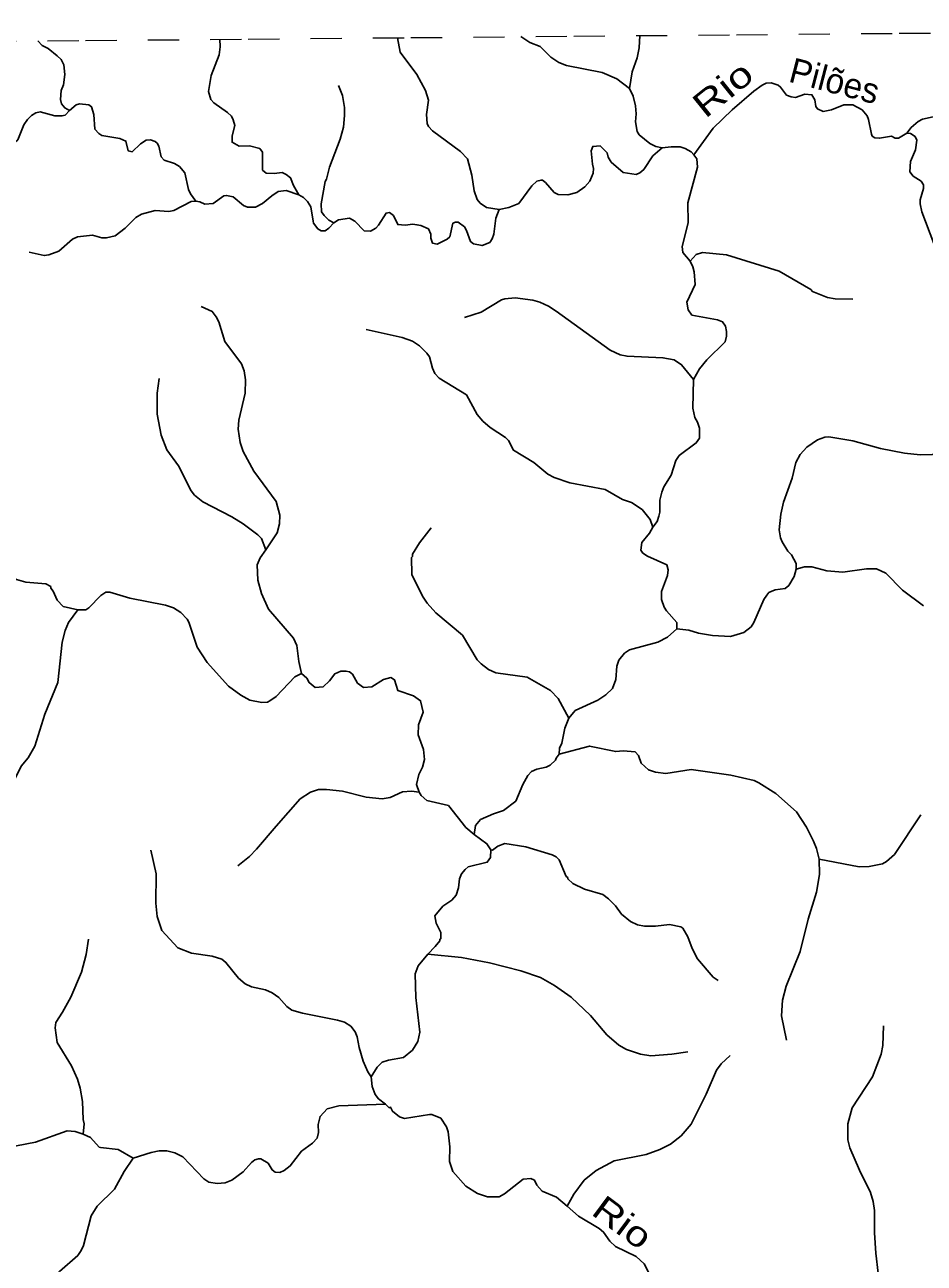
# Model space of a CAD drawing. Extents: x 346.5 to 372.4, y 7400.3 to 7428.2.
# Drawn here: x 366.191 to 369.076, y 7424.274 to 7428.245 of the extents above; entities that cross this region are included whole.
import ezdxf
from ezdxf.enums import TextEntityAlignment as Align

# ---------------------------------------------------------------- set-up
doc = ezdxf.new("R2010")
doc.units = 0
doc.header["$LTSCALE"] = 0.032
doc.linetypes.add('SHORT_DASHED', pattern=[2.7, 1.5, -1.2])
doc.layers.add('53', color=7, linetype='SHORT_DASHED', lineweight=13)
doc.layers.add('7', color=7, linetype='Continuous', lineweight=25)
doc.layers.add('61', color=7, linetype='Continuous')

msp = doc.modelspace()

# ---------------------------------------------------------------- linework, layer by layer
at = {"layer": '53'}
msp.add_lwpolyline([(361.6878, 7428.1517), (362.2098, 7428.1565), (362.7318, 7428.1614), (363.2538, 7428.1662), (363.7758, 7428.171), (364.2978, 7428.1758), (364.8198, 7428.1805), (365.3418, 7428.1853), (365.8638, 7428.19), (366.3858, 7428.1947), (366.9078, 7428.1994), (367.4298, 7428.2041), (367.9518, 7428.2087), (368.4738, 7428.2133), (368.9958, 7428.218), (369.5177, 7428.2225), (370.0397, 7428.2271), (370.5617, 7428.2317), (371.0837, 7428.2362), (371.6057, 7428.2408), (372.1277, 7428.2453)], dxfattribs=at)
at = {"layer": '7'}
for points in [[(366.2331, 7428.1933), (366.2471, 7428.1793), (366.2654, 7428.169), (366.2949, 7428.1459), (366.3076, 7428.1339), (366.3164, 7428.1172), (366.3196, 7428.0853), (366.3156, 7428.0526), (366.3076, 7428.0343), (366.3052, 7428.0056), (366.3084, 7427.9913), (366.3191, 7427.9786), (366.3339, 7427.9699)], [(366.8162, 7428.1986), (366.8177, 7428.1746), (366.8145, 7428.1491), (366.789, 7428.0821), (366.7802, 7428.0311), (366.7874, 7428.0056), (366.797, 7427.9953), (366.8416, 7427.9642), (366.8543, 7427.9522), (366.8599, 7427.9403), (366.8647, 7427.9219), (366.8567, 7427.8893), (366.8559, 7427.8685), (366.879, 7427.8558), (366.9117, 7427.8566), (366.9444, 7427.8486), (366.954, 7427.8367), (366.9532, 7427.7793), (366.9651, 7427.7697), (366.9914, 7427.7681), (367.0169, 7427.7713), (367.0297, 7427.7649), (367.0432, 7427.7546), (367.0528, 7427.7299), (367.0697, 7427.7)], [(367.3864, 7428.2037), (367.3947, 7428.157), (367.4489, 7428.0853), (367.4767, 7428.0343), (367.4855, 7428.004), (367.4791, 7427.9578), (367.4815, 7427.9291), (367.4855, 7427.9187), (367.4983, 7427.9052), (367.5883, 7427.8391), (367.6114, 7427.8151), (367.625, 7427.7634), (367.6321, 7427.7123), (367.6417, 7427.6852), (367.6521, 7427.6733), (367.672, 7427.6589), (367.7128, 7427.6526)], [(367.7823, 7428.2072), (367.8107, 7428.1881), (367.8442, 7428.1754), (367.8784, 7428.1411), (367.9039, 7428.1244), (367.9286, 7428.1148), (368.0434, 7428.0925), (368.0904, 7428.0718), (368.1312, 7428.0405)], [(368.1636, 7428.2105), (368.1613, 7428.1714), (368.1549, 7428.1395), (368.139, 7428.0949), (368.1312, 7428.0405)], [(367.197, 7428.051), (367.2098, 7428.0184), (367.2161, 7427.9801), (367.2169, 7427.9546), (367.213, 7427.9164), (367.2026, 7427.8781), (367.1683, 7427.7889), (367.1588, 7427.7506), (367.154, 7427.7426), (367.142, 7427.6709), (367.1428, 7427.6454), (367.1508, 7427.6334), (367.1667, 7427.6191), (367.1828, 7427.6098)], [(368.1312, 7428.0405), (368.1422, 7428.016), (368.1502, 7427.9849), (368.1526, 7427.9594), (368.1502, 7427.9339), (368.1549, 7427.9028), (368.1613, 7427.8925), (368.1964, 7427.8645), (368.2155, 7427.855), (368.2352, 7427.8506)], [(369.0208, 7427.8978), (368.9934, 7427.8813), (368.983, 7427.8813), (368.971, 7427.8877), (368.9328, 7427.8813), (368.9176, 7427.8829), (368.9089, 7427.8885), (368.9065, 7427.8941), (368.8977, 7427.9419), (368.8929, 7427.9538), (368.877, 7427.9721), (368.8467, 7427.9881), (368.818, 7427.9889), (368.7782, 7427.9721), (368.7519, 7427.9674), (368.7335, 7427.9753), (368.7288, 7427.9833), (368.7256, 7428.0048), (368.716, 7428.0207), (368.6937, 7428.0223), (368.6634, 7428.012), (368.6491, 7428.0144), (368.6347, 7428.0192), (368.6156, 7428.0454), (368.6076, 7428.0518), (368.5853, 7428.059), (368.5694, 7428.0582), (368.5558, 7428.0518), (368.5295, 7428.0327), (368.4602, 7427.9721), (368.3996, 7427.9132), (368.3373, 7427.8283)], [(366.3339, 7427.9699), (366.3204, 7427.9554), (366.31, 7427.953), (366.2869, 7427.9538), (366.2407, 7427.9658), (366.2263, 7427.9626), (366.2128, 7427.9546), (366.2, 7427.9419), (366.1881, 7427.9243), (366.1682, 7427.8765), (366.1602, 7427.8685), (366.1275, 7427.8494), (366.0765, 7427.8279), (366.0231, 7427.7992), (366.0007, 7427.7855), (365.9865, 7427.7783)], [(366.7396, 7427.6792), (366.722, 7427.7028), (366.7157, 7427.7171), (366.7045, 7427.7705), (366.687, 7427.7904), (366.6711, 7427.8), (366.6376, 7427.8112), (366.6288, 7427.8223), (366.6208, 7427.8558), (366.6153, 7427.8661), (366.6089, 7427.8709), (366.5945, 7427.8765), (366.5802, 7427.8749), (366.5619, 7427.863), (366.5356, 7427.8382), (366.5228, 7427.8406), (366.5156, 7427.8725), (366.4957, 7427.8805), (366.4383, 7427.8901), (366.428, 7427.8964), (366.416, 7427.91), (366.4128, 7427.9578), (366.4049, 7427.9825), (366.3969, 7427.9881), (366.3666, 7427.9921), (366.3562, 7427.9881), (366.3339, 7427.9699)], [(369.1045, 7427.9498), (369.0706, 7427.9426), (369.0571, 7427.9347), (369.0347, 7427.9155), (369.0208, 7427.8978)], [(369.0208, 7427.8978), (369.0316, 7427.8964), (369.0467, 7427.8869), (369.0523, 7427.8757), (369.0483, 7427.8446), (369.0316, 7427.8064), (369.03, 7427.7737), (369.0412, 7427.7601), (369.0667, 7427.7434), (369.0738, 7427.7315), (369.0738, 7427.7203), (369.0635, 7427.6837), (369.0627, 7427.6709), (369.0682, 7427.6454), (369.1073, 7427.5434)], [(367.7128, 7427.6526), (367.7437, 7427.6589), (367.7756, 7427.6717), (367.817, 7427.7283), (367.8338, 7427.7442), (367.8473, 7427.7474), (367.8521, 7427.7474), (367.8617, 7427.7394), (367.8888, 7427.7076), (367.9015, 7427.7012), (367.9334, 7427.7004), (367.9621, 7427.7075), (367.9876, 7427.7251), (368.0035, 7427.7434), (368.0139, 7427.7697), (368.0155, 7427.7841), (368.0123, 7427.7984), (368.0075, 7427.8415), (368.0131, 7427.855), (368.037, 7427.8566), (368.0593, 7427.8343), (368.0625, 7427.8207), (368.0721, 7427.8048), (368.1103, 7427.7713), (368.1518, 7427.7649), (368.1637, 7427.7705), (368.1765, 7427.7817), (368.2052, 7427.8247), (368.2352, 7427.8506)], [(368.2352, 7427.8506), (368.2649, 7427.8542), (368.2936, 7427.8534), (368.3096, 7427.8486), (368.3287, 7427.8375), (368.3373, 7427.8283)], [(368.3373, 7427.8283), (368.3469, 7427.8152), (368.3486, 7427.7889), (368.3183, 7427.6741), (368.3191, 7427.6103), (368.3, 7427.5338), (368.3016, 7427.5147), (368.3252, 7427.487)], [(366.7396, 7427.6792), (366.7244, 7427.6787), (366.6695, 7427.6502), (366.6535, 7427.647), (366.6089, 7427.6502), (366.565, 7427.6382), (366.5475, 7427.6271), (366.5132, 7427.5928), (366.4806, 7427.5681), (366.4527, 7427.5625), (366.4383, 7427.5625), (366.4081, 7427.5705), (366.3602, 7427.5649), (366.3443, 7427.5577), (366.2997, 7427.5195), (366.2678, 7427.5075), (366.2535, 7427.5051), (366.2048, 7427.5163)], [(367.0697, 7427.7), (367.0297, 7427.7139), (367.0042, 7427.7107), (366.9835, 7427.6972), (366.954, 7427.6717), (366.9309, 7427.6605), (366.9054, 7427.6605), (366.8926, 7427.6661), (366.8599, 7427.694), (366.8384, 7427.698), (366.8296, 7427.6972), (366.7954, 7427.6717), (366.7685, 7427.6697), (366.7526, 7427.678), (366.7396, 7427.6792)], [(367.1828, 7427.6098), (367.1667, 7427.5928), (367.154, 7427.5848), (367.1412, 7427.5848), (367.1309, 7427.5904), (367.1173, 7427.6087), (367.1165, 7427.6159), (367.1086, 7427.6613), (367.0982, 7427.6781), (367.085, 7427.6916), (367.0697, 7427.7)], [(367.7128, 7427.6526), (367.7015, 7427.6247), (367.6959, 7427.5737), (367.6903, 7427.5585), (367.6824, 7427.5474), (367.6577, 7427.537), (367.6306, 7427.5426), (367.621, 7427.5498), (367.6082, 7427.5856), (367.6011, 7427.5968), (367.5812, 7427.6127), (367.5724, 7427.6127), (367.5644, 7427.6087), (367.5549, 7427.5657), (367.5461, 7427.5577), (367.5142, 7427.5418), (367.4983, 7427.545), (367.4935, 7427.5609), (367.4935, 7427.5737), (367.4855, 7427.5904), (367.4616, 7427.6016), (367.4489, 7427.6039), (367.4361, 7427.6055), (367.4106, 7427.6023), (367.3875, 7427.6047), (367.374, 7427.6334), (367.3612, 7427.6438), (367.35, 7427.6414), (367.3261, 7427.6024), (367.3174, 7427.5928), (367.2998, 7427.5832), (367.2799, 7427.5848), (367.2496, 7427.6159), (367.2329, 7427.6247), (367.1973, 7427.6202), (367.1828, 7427.6098)], [(368.3252, 7427.487), (368.3341, 7427.4691), (368.3382, 7427.4525), (368.3414, 7427.4119), (368.3151, 7427.3561), (368.3191, 7427.3314), (368.3311, 7427.3138), (368.4132, 7427.2995), (368.4291, 7427.2923), (368.4387, 7427.2788), (368.4418, 7427.2613), (368.4418, 7427.2469), (368.4371, 7427.2286), (368.3789, 7427.1712), (368.3558, 7427.1417), (368.3364, 7427.1079)], [(368.3252, 7427.487), (368.3446, 7427.5083), (368.3654, 7427.5155), (368.4419, 7427.5075), (368.6108, 7427.4549), (368.7128, 7427.3959), (368.7176, 7427.3904), (368.7654, 7427.3712), (368.7909, 7427.3665), (368.8475, 7427.3649)], [(367.6011, 7427.3067), (367.6545, 7427.3242), (367.7198, 7427.3633), (367.731, 7427.3665), (367.7645, 7427.3696), (367.8202, 7427.3625), (367.8426, 7427.3561), (367.8705, 7427.3433), (367.8951, 7427.3274), (368.0689, 7427.2015), (368.1008, 7427.1871), (368.1231, 7427.1824), (368.2378, 7427.1776), (368.2745, 7427.1712), (368.2976, 7427.1553), (368.3364, 7427.1079)], [(366.7563, 7427.3418), (366.7922, 7427.3258), (366.8049, 7427.3091), (366.8137, 7427.2932), (366.8328, 7427.2294), (366.8862, 7427.1585), (366.8942, 7427.1354), (366.899, 7427.1067), (366.8974, 7427.0636), (366.8774, 7426.9776), (366.8751, 7426.9489), (366.8814, 7426.9058), (366.891, 7426.8771), (366.9261, 7426.8134), (366.997, 7426.7162), (367.0089, 7426.6731), (367.0081, 7426.6444), (367.001, 7426.6157), (366.9646, 7426.5619)], [(367.2855, 7427.2677), (367.4011, 7427.2429), (367.4345, 7427.2302), (367.4568, 7427.2158), (367.4807, 7427.1927), (367.4887, 7427.18), (367.4983, 7427.1441), (367.5062, 7427.1266), (367.5206, 7427.1122), (367.6074, 7427.0581), (367.6425, 7426.9959), (367.6601, 7426.9744), (367.684, 7426.9536), (367.7334, 7426.9218), (367.7421, 7426.9122), (367.7581, 7426.8811), (367.8242, 7426.8421), (367.8689, 7426.8038), (367.8888, 7426.7935), (367.9398, 7426.7759), (368.0522, 7426.7552), (368.1087, 7426.7233), (368.1374, 7426.713), (368.1709, 7426.6906), (368.1972, 7426.6588), (368.2053, 7426.6343)], [(366.6216, 7427.1106), (366.6153, 7427.0636), (366.6153, 7426.9967), (366.6288, 7426.9297), (366.6463, 7426.8819), (366.6838, 7426.8309), (366.7244, 7426.7504), (366.7356, 7426.7369), (366.7619, 7426.7154), (366.8551, 7426.6675), (366.891, 7426.6452), (366.938, 7426.6094), (366.95, 7426.5974), (366.9646, 7426.5619)], [(368.3364, 7427.1079), (368.3343, 7427.0158), (368.3398, 7426.9855), (368.3494, 7426.9704), (368.3558, 7426.9521), (368.3558, 7426.9194), (368.3446, 7426.9042), (368.2896, 7426.8636), (368.2793, 7426.8477), (368.2641, 7426.8006), (368.241, 7426.7632), (368.2346, 7426.7464), (368.2283, 7426.7209), (368.2283, 7426.6827), (368.2251, 7426.6699), (368.2195, 7426.6524), (368.2053, 7426.6343)], [(369.2763, 7426.9704), (369.1527, 7426.8787), (369.1017, 7426.8668), (369.0635, 7426.866), (369.0125, 7426.8716), (368.936, 7426.8867), (368.8467, 7426.9114), (368.7702, 7426.9234), (368.7575, 7426.9226), (368.7335, 7426.9146), (368.6993, 7426.8907), (368.6785, 7426.8676), (368.6642, 7426.8421), (368.653, 7426.7911), (368.6251, 7426.7146), (368.6164, 7426.6763), (368.6108, 7426.6253), (368.6148, 7426.5998), (368.6204, 7426.5871), (368.6387, 7426.5576), (368.6499, 7426.5456), (368.6652, 7426.5179), (368.6652, 7426.5)], [(367.4943, 7426.6325), (367.4568, 7426.5839), (367.4345, 7426.5472), (367.4345, 7426.54), (367.4313, 7426.5368), (367.4321, 7426.4819), (367.4672, 7426.4125), (367.4815, 7426.3902), (367.5094, 7426.3591), (367.5955, 7426.2874), (367.6425, 7426.2085), (367.6545, 7426.1958), (367.6784, 7426.1782), (367.7023, 7426.1671), (367.8027, 7426.1535), (367.8776, 7426.1105), (367.9023, 7426.085), (367.9357, 7426.0221)], [(368.2053, 7426.6343), (368.1948, 7426.6149), (368.1701, 7426.5847), (368.1669, 7426.56), (368.1733, 7426.5512), (368.1884, 7426.5408), (368.2506, 7426.5129), (368.2546, 7426.4978), (368.2522, 7426.4787), (368.233, 7426.4277), (368.2338, 7426.4022), (368.2418, 7426.3775), (368.249, 7426.3655), (368.2825, 7426.328), (368.2821, 7426.3085)], [(366.1215, 7426.5691), (366.1215, 7426.5374), (366.1076, 7426.5145), (366.11, 7426.4946), (366.1355, 7426.4779), (366.1642, 7426.4659), (366.1945, 7426.4579), (366.2582, 7426.4524), (366.2742, 7426.4436), (366.2742, 7426.4388), (366.2821, 7426.4293), (366.2949, 7426.4006), (366.314, 7426.3798), (366.3611, 7426.3686)], [(366.9646, 7426.5619), (366.946, 7426.5361), (366.9364, 7426.5129), (366.9388, 7426.4643), (366.95, 7426.4213), (366.9723, 7426.3711), (367.0528, 7426.2778), (367.0631, 7426.2547), (367.0695, 7426.2029), (367.0783, 7426.1645)], [(368.6652, 7426.5), (368.6586, 7426.4755), (368.6419, 7426.4476), (368.6299, 7426.438), (368.5981, 7426.4332), (368.5853, 7426.4277), (368.5781, 7426.4245), (368.5717, 7426.4165), (368.5614, 7426.4022), (368.5295, 7426.3288), (368.5208, 7426.3145), (368.4977, 7426.2962), (368.4546, 7426.2834), (368.3972, 7426.2866), (368.3526, 7426.2946), (368.3207, 7426.3041), (368.2821, 7426.3085)], [(369.0738, 7426.3822), (369.0069, 7426.4324), (368.9535, 7426.4866), (368.9232, 7426.5002), (368.8913, 7426.5002), (368.8148, 7426.4898), (368.7638, 7426.4938), (368.7152, 7426.5073), (368.6921, 7426.5073), (368.6652, 7426.5)], [(366.3611, 7426.3686), (366.3865, 7426.3695), (366.3969, 7426.3751), (366.4351, 7426.4149), (366.4511, 7426.4253), (366.4638, 7426.4261), (366.5276, 7426.4061), (366.6424, 7426.3846), (366.6679, 7426.3758), (366.6918, 7426.3607), (366.7117, 7426.3392), (366.7173, 7426.3296), (366.7436, 7426.2492), (366.7762, 7426.1997), (366.844, 7426.1248), (366.8838, 7426.0953), (366.9133, 7426.0794), (366.9516, 7426.0722), (366.9691, 7426.073), (366.9771, 7426.077), (366.9978, 7426.0913), (367.0568, 7426.1543), (367.0783, 7426.1645)], [(366.3611, 7426.3686), (366.3307, 7426.3288), (366.3204, 7426.3033), (366.3108, 7426.2651), (366.2973, 7426.136), (366.255, 7426.034), (366.2231, 7425.932), (366.2016, 7425.8945), (366.1793, 7425.8682), (366.1546, 7425.8172), (366.1403, 7425.7662), (366.1323, 7425.7184), (366.1323, 7425.653), (366.1259, 7425.5893), (366.114, 7425.551), (366.0853, 7425.5088)], [(368.2821, 7426.3085), (368.2522, 7426.281), (368.2219, 7426.2659), (368.1303, 7426.2412), (368.1151, 7426.23), (368.096, 7426.2077), (368.0904, 7426.1886), (368.0864, 7426.1456), (368.0761, 7426.1168), (368.0545, 7426.0961), (368.029, 7426.0794), (367.9565, 7426.0459), (367.9357, 7426.0221)], [(367.0783, 7426.1645), (367.0958, 7426.1495), (367.103, 7426.136), (367.1221, 7426.12), (367.1476, 7426.1224), (367.1683, 7426.1416), (367.1851, 7426.1639), (367.205, 7426.1726), (367.2209, 7426.1726), (367.2321, 7426.1702), (367.2417, 7426.1623), (367.2584, 7426.1344), (367.2775, 7426.12), (367.3046, 7426.1224), (367.3421, 7426.1455), (367.3652, 7426.1519), (367.3771, 7426.1447), (367.3875, 7426.1105), (367.4377, 7426.0929), (367.4608, 7426.0778), (367.4688, 7426.0411), (367.4544, 7426.0005), (367.4528, 7425.9686), (367.4696, 7425.9208), (367.4736, 7425.8889), (367.4664, 7425.8642), (367.4552, 7425.8411), (367.4474, 7425.8092), (367.4556, 7425.7844)], [(367.9357, 7426.0221), (367.9238, 7425.9893), (367.9135, 7425.9415), (367.9067, 7425.9252), (367.9047, 7425.9066)], [(368.7387, 7425.5699), (368.7311, 7425.6036), (368.7208, 7425.6275), (368.6985, 7425.6722), (368.6666, 7425.7216), (368.5997, 7425.7805), (368.5455, 7425.8148), (368.5303, 7425.822), (368.4562, 7425.8387), (368.3287, 7425.857), (368.2474, 7425.8443), (368.2139, 7425.8483), (368.1916, 7425.8562), (368.1685, 7425.8778), (368.1597, 7425.9017), (368.1486, 7425.9136), (368.1103, 7425.9168), (368.0864, 7425.9144), (368.0027, 7425.932), (367.9047, 7425.9066)], [(367.9047, 7425.9066), (367.8951, 7425.8937), (367.8936, 7425.8865), (367.876, 7425.8714), (367.8633, 7425.8642), (367.833, 7425.8578), (367.8162, 7425.8507), (367.8051, 7425.8379), (367.7884, 7425.8092), (367.766, 7425.7558), (367.7262, 7425.7255), (367.6943, 7425.7152), (367.6529, 7425.6969), (367.637, 7425.6776), (367.6328, 7425.6484)], [(367.4556, 7425.7844), (367.4314, 7425.7872), (367.4025, 7425.7858), (367.3628, 7425.7678), (367.3373, 7425.763), (367.2863, 7425.7686), (367.2098, 7425.7877), (367.1588, 7425.7933), (367.1333, 7425.7925), (367.1078, 7425.7845), (367.0743, 7425.763), (366.9978, 7425.6754), (366.934, 7425.6012), (366.9117, 7425.5781), (366.8743, 7425.5486)], [(367.6328, 7425.6484), (367.6059, 7425.6714), (367.5501, 7425.7415), (367.481, 7425.7582), (367.4624, 7425.7734), (367.4556, 7425.7844)], [(369.0651, 7425.7112), (368.9806, 7425.5845), (368.9551, 7425.5622), (368.9423, 7425.555), (368.8993, 7425.5462), (368.8674, 7425.5454), (368.7387, 7425.5699)], [(367.6859, 7425.5992), (367.6736, 7425.6188), (367.6328, 7425.6484)], [(368.4152, 7425.1807), (368.3988, 7425.1916), (368.3486, 7425.2498), (368.3319, 7425.2833), (368.3183, 7425.3207), (368.3016, 7425.3478), (368.2952, 7425.3526), (368.2586, 7425.3605), (368.2139, 7425.3542), (368.1789, 7425.3542), (368.1566, 7425.359), (368.1342, 7425.3701), (368.1055, 7425.3932), (368.0856, 7425.4195), (368.0633, 7425.4426), (368.045, 7425.4562), (367.986, 7425.4737), (367.9493, 7425.492), (367.9326, 7425.5064), (367.9326, 7425.5104), (367.9278, 7425.5144), (367.9055, 7425.567), (367.8951, 7425.5773), (367.8824, 7425.5837), (367.7979, 7425.6092), (367.731, 7425.6195), (367.7087, 7425.6116), (367.6911, 7425.5988), (367.6859, 7425.5992)], [(366.5953, 7425.598), (366.6121, 7425.5223), (366.6113, 7425.4283), (366.6153, 7425.3853), (366.6304, 7425.3406), (366.6814, 7425.2848), (366.7252, 7425.2681), (366.7922, 7425.2585), (366.8233, 7425.249), (366.836, 7425.2386), (366.8766, 7425.1876), (366.8974, 7425.1701), (366.9181, 7425.1597), (366.9627, 7425.1502), (366.985, 7425.1406), (367.0058, 7425.1254), (367.0312, 7425.0968), (367.0472, 7425.0848), (367.0823, 7425.0752), (367.1938, 7425.0537), (367.2162, 7425.0465), (367.2369, 7425.0338), (367.2512, 7425.0163), (367.2568, 7424.9995), (367.2632, 7424.9661), (367.2767, 7424.9214), (367.2911, 7424.888), (367.3024, 7424.8713)], [(367.4833, 7425.2653), (367.5078, 7425.2896), (367.5222, 7425.308), (367.5222, 7425.3127), (367.5254, 7425.3143), (367.5254, 7425.3343), (367.5102, 7425.3645), (367.5062, 7425.3877), (367.5317, 7425.4187), (367.5604, 7425.4379), (367.5748, 7425.4546), (367.5827, 7425.4777), (367.5859, 7425.5064), (367.5923, 7425.5223), (367.6035, 7425.5367), (367.613, 7425.5446), (367.6744, 7425.5598), (367.6845, 7425.5744), (367.6859, 7425.5992)], [(368.6347, 7424.9892), (368.6188, 7425.0673), (368.622, 7425.1175), (368.6331, 7425.1621), (368.6785, 7425.2737), (368.704, 7425.3773), (368.7311, 7425.4634), (368.7399, 7425.5207), (368.7387, 7425.5699)], [(366.3953, 7425.3127), (366.3881, 7425.2641), (366.373, 7425.2067), (366.3387, 7425.1271), (366.3124, 7425.0792), (366.2901, 7425.0458), (366.2885, 7425.0282), (366.2949, 7424.982), (366.3411, 7424.9071), (366.3602, 7424.8641), (366.369, 7424.8354), (366.3762, 7424.7923), (366.3778, 7424.735), (366.3809, 7424.721), (366.3787, 7424.6875)], [(367.3024, 7424.8713), (367.3213, 7424.9023), (367.3373, 7424.919), (367.358, 7424.9254), (367.4058, 7424.9334), (367.4345, 7424.9565), (367.452, 7424.9852), (367.4584, 7425.0147), (367.4457, 7425.1255), (367.4433, 7425.202), (367.4528, 7425.2275), (367.4833, 7425.2653)], [(367.4833, 7425.2653), (367.5923, 7425.2538), (367.6816, 7425.237), (367.782, 7425.2115), (367.8449, 7425.19), (367.8904, 7425.1645), (367.9438, 7425.127), (368.0051, 7425.0681), (368.0577, 7425.0067), (368.0968, 7424.9732), (368.1215, 7424.9589), (368.1661, 7424.9445), (368.1996, 7424.939), (368.2665, 7424.9437), (368.3183, 7424.9517)], [(368.9455, 7425.0354), (368.9439, 7424.9724), (368.9376, 7424.9438), (368.9097, 7424.872), (368.8451, 7424.7716), (368.8308, 7424.7206), (368.8316, 7424.6696), (368.8379, 7424.6441), (368.8682, 7424.5724), (368.9041, 7424.5007), (368.912, 7424.472), (368.9168, 7424.4433), (368.9168, 7424.3716), (368.9208, 7424.3062), (368.9288, 7424.2424), (368.928, 7424.2209), (368.9407, 7424.142), (368.9487, 7424.1133), (368.9694, 7424.0703), (368.991, 7424.048), (369.0147, 7424.03)], [(368.4538, 7424.9398), (368.4243, 7424.9127), (368.41, 7424.8928), (368.3765, 7424.8162), (368.3287, 7424.7198), (368.296, 7424.6824), (368.2618, 7424.656), (368.2283, 7424.6385), (368.1837, 7424.6226), (368.0816, 7424.6019), (368.0235, 7424.5716), (367.9852, 7424.5397), (367.9517, 7424.4951), (367.9309, 7424.457)], [(367.3475, 7424.7839), (367.3257, 7424.8006), (367.315, 7424.8147), (367.3054, 7424.8402), (367.3024, 7424.8713)], [(367.3475, 7424.7839), (367.1986, 7424.7788), (367.1604, 7424.7684), (367.138, 7424.7445), (367.1325, 7424.719), (367.1333, 7424.6935), (367.1285, 7424.6752), (367.1141, 7424.6584), (367.0783, 7424.6329), (367.0424, 7424.5859), (367.0233, 7424.5708), (367.0089, 7424.5644), (366.9946, 7424.566), (366.9842, 7424.5732), (366.9715, 7424.5947), (366.9476, 7424.609), (366.9404, 7424.609), (366.9293, 7424.605), (366.9181, 7424.5963), (366.891, 7424.5668), (366.8551, 7424.5397), (366.8336, 7424.5317), (366.8081, 7424.5293), (366.781, 7424.5333), (366.7651, 7424.5445), (366.6981, 7424.6146), (366.6726, 7424.6274), (366.6471, 7424.6337), (366.6216, 7424.6337), (366.5961, 7424.6289), (366.5389, 7424.6109)], [(367.9309, 7424.457), (367.8968, 7424.4855), (367.8505, 7424.5046), (367.833, 7424.5238), (367.8258, 7424.5397), (367.8146, 7424.5453), (367.79, 7424.5437), (367.7302, 7424.4967), (367.7127, 7424.4871), (367.6752, 7424.4871), (367.6433, 7424.4974), (367.6059, 7424.5206), (367.5644, 7424.5676), (367.5533, 7424.5995), (367.554, 7424.6473), (367.5493, 7424.6951), (367.5437, 7424.711), (367.5254, 7424.7389), (367.4967, 7424.7509), (367.4887, 7424.7509), (367.409, 7424.7381), (367.3931, 7424.7429), (367.37, 7424.7612), (367.3644, 7424.774), (367.3601, 7424.7724), (367.3475, 7424.7839)], [(366.3787, 7424.6875), (366.3523, 7424.6967), (366.3268, 7424.6983), (366.2248, 7424.6616), (366.0973, 7424.6369), (366.059, 7424.6369), (366.008, 7424.6513), (365.9729, 7424.6513), (365.9482, 7424.6321), (365.9243, 7424.6066), (365.8932, 7424.5979), (365.8701, 7424.5979), (365.8319, 7424.6242), (365.8111, 7424.6664), (365.7928, 7424.6919), (365.7689, 7424.7126), (365.7434, 7424.7254), (365.6924, 7424.7405), (365.6541, 7424.7405), (365.6031, 7424.7349), (365.5505, 7424.7357), (365.49, 7424.7514)], [(366.5389, 7424.6109), (366.4909, 7424.6385), (366.4336, 7424.6449), (366.4296, 7424.6457), (366.4017, 7424.6767), (366.3787, 7424.6875)], [(366.5389, 7424.6109), (366.51, 7424.5676), (366.4782, 7424.511), (366.4232, 7424.4568), (366.4041, 7424.4257), (366.3794, 7424.3301), (366.3722, 7424.3142), (366.361, 7424.299), (366.3021, 7424.2472), (366.2711, 7424.2029), (366.2642, 7424.1808)], [(368.2403, 7424.1977), (368.2259, 7424.2046), (368.2107, 7424.2169), (368.1964, 7424.2361), (368.1773, 7424.2719), (368.1518, 7424.295), (368.0856, 7424.3269), (368.0673, 7424.3445), (368.0474, 7424.3739), (368.0338, 7424.3851), (367.9669, 7424.4249), (367.9309, 7424.457)]]:
    msp.add_lwpolyline(points, dxfattribs=at)

# ---------------------------------------------------------------- texts
at = {"layer": '61'}
msp.add_text('Pilões', height=0.08, rotation=345.384, dxfattribs=at).set_placement((368.7785, 7428.0268), align=Align.CENTER)
for rotation, width, p in [(38.894, 1.3, (368.4551, 7428.0081)), (323.352, 1.25, (368.0847, 7424.3727))]:
    msp.add_text('Rio', height=0.08, rotation=rotation, dxfattribs=dict(at, width=width)).set_placement(p, align=Align.CENTER)

doc.saveas('drawing.dxf')
